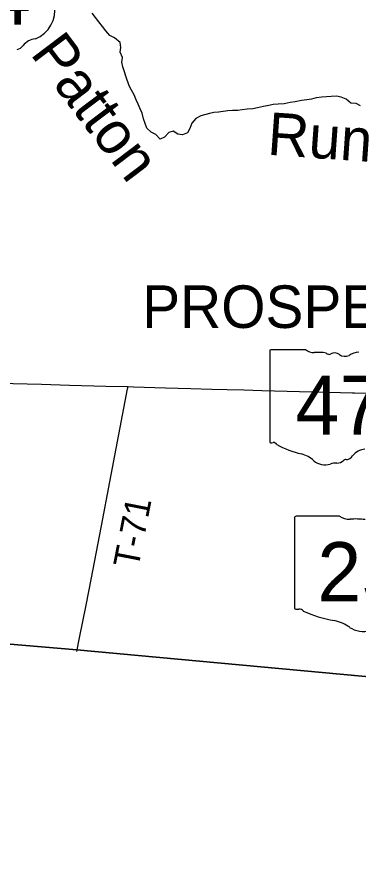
# Model space of a CAD drawing. Extents: x 1584893 to 1934202, y 663575 to 1091909.
# Drawn here: x 1770966 to 1774979, y 887388 to 897514 of the extents above; entities that cross this region are included whole.
import ezdxf

# ---------------------------------------------------------------- set-up
doc = ezdxf.new("R2010")
doc.units = 0
for name, color, linetype in [('GM_X_Adjacent_County', 7, 'Continuous'), ('GM_X_Corporation_Text', 7, 'Continuous'), ('GM_X_County', 7, 'Continuous'), ('GM_X_Minor_River', 7, 'Continuous'), ('GM_X_Minor_River_Text', 7, 'Continuous'), ('GM_X_State_Location', 7, 'Continuous'), ('GM_X_State_Route', 7, 'Continuous'), ('GM_X_State_Shield', 7, 'Continuous'), ('GM_X_Township', 7, 'Continuous'), ('GM_X_Township_Road', 7, 'Continuous'), ('GM_X_Township_Road_Text', 7, 'Continuous')]:
    doc.layers.add(name, color=color, linetype=linetype)

msp = doc.modelspace()

# ---------------------------------------------------------------- linework, layer by layer
at = {"layer": 'GM_X_Adjacent_County'}
msp.add_lwpolyline([(1760161, 891042), (1765804, 890577), (1771666, 890080), (1775269, 889747), (1775894, 889674), (1776032, 889658), (1778209, 889456), (1784657, 889014), (1789933, 888711), (1791146, 888682), (1797651, 888237), (1803655, 887971), (1808445, 887685), (1809126, 887642), (1809339, 887629), (1813443, 887429), (1813717, 887422), (1814360, 887388)], dxfattribs=at)
at = {"layer": 'GM_X_County'}
msp.add_lwpolyline([(1814360, 887388), (1813717, 887422), (1813443, 887429), (1809339, 887629), (1809126, 887642), (1808445, 887685), (1803655, 887971), (1797651, 888237), (1791146, 888682), (1789933, 888711), (1784657, 889014), (1778209, 889456), (1776032, 889658), (1775894, 889674), (1775269, 889747), (1771666, 890080), (1765804, 890577), (1760161, 891042)], dxfattribs=at)
at = {"layer": 'GM_X_Minor_River'}
for points in [[(1773669, 896432), (1773609, 896427), (1773557, 896419), (1773495, 896416), (1773439, 896413), (1773385, 896406), (1773331, 896397), (1773277, 896394), (1773227, 896384), (1773123, 896354), (1773063, 896325), (1773016, 896269), (1772995, 896207), (1772966, 896154), (1772908, 896131), (1772852, 896139), (1772799, 896174), (1772747, 896159), (1772696, 896106), (1772646, 896082), (1772595, 896135), (1772539, 896162), (1772488, 896209), (1772471, 896263), (1772450, 896320), (1772435, 896386), (1772409, 896437), (1772386, 896491), (1772365, 896542), (1772338, 896602), (1772307, 896655), (1772281, 896707), (1772243, 896820), (1772228, 896870), (1772207, 896929), (1772196, 896985), (1772204, 897041), (1772175, 897104), (1772182, 897158), (1772175, 897216), (1772110, 897273), (1772052, 897298), (1772005, 897353), (1771968, 897403), (1771925, 897458), (1771886, 897511), (1771847, 897561)], [(1774999, 896472), (1774948, 896501), (1774888, 896504), (1774833, 896549), (1774771, 896576), (1774716, 896584), (1774654, 896583), (1774600, 896578), (1774544, 896575), (1774478, 896568), (1774422, 896551), (1774368, 896544), (1774306, 896534), (1774231, 896520), (1774173, 896512), (1774101, 896497), (1774033, 896492), (1773973, 896487), (1773923, 896476), (1773859, 896463), (1773791, 896448), (1773735, 896439), (1773669, 896432)]]:
    msp.add_lwpolyline(points, dxfattribs=at)
at = {"layer": 'GM_X_State_Route'}
for points in [[(1770744, 893212), (1771252, 893200), (1771580, 893191), (1772006, 893179), (1772268, 893172), (1772334, 893170), (1772710, 893159), (1773005, 893150), (1773251, 893144), (1773431, 893140), (1773628, 893134), (1773841, 893127), (1774136, 893119), (1774283, 893116), (1774480, 893111), (1774906, 893099), (1774928, 893098)], [(1774928, 893098), (1775070, 893095), (1775201, 893089), (1775299, 893086), (1775403, 893085)]]:
    msp.add_lwpolyline(points, dxfattribs=at)
at = {"layer": 'GM_X_State_Shield'}
for p, q in [((1773933, 893588), (1773933, 892531)), ((1774354, 893606), (1773946, 893606)), ((1774751, 891648), (1774242, 891648)), ((1774225, 891630), (1774225, 890573))]:
    msp.add_line(p, q, dxfattribs=at)
for centre, radius, start, end in [((1771040, 897600), 369, 292.3089, 8.9858), ((1771195, 897057), 202, 94.4031, 142.5768), ((1770939, 897251), 119, 282.8732, 323.2771), ((1773949, 893590), 16.1, 98.1301, 188.1301), ((1774451, 893729), 156, 231.6195, 271.1119), ((1774503, 893013), 562, 80.4867, 94.9883), ((1774631, 893596), 45.1, 219.7921, 297.1024), ((1774697, 893474), 93.8, 54.4667, 119.1411), ((1775017, 893283), 297, 97.3462, 120.7689), ((1774818, 893641), 113, 233.8562, 294.8282), ((1773949, 892529), 16.3, 171.9584, 258.3066), ((1773951, 892637), 124, 267.339, 280.6039), ((1773977, 892470), 44.8, 29.7484, 93.2717), ((1774542, 893420), 1066, 240.4129, 257.1985), ((1774224, 892057), 334, 47.1842, 75.836), ((1774811, 892429), 119, 282.8732, 323.2771), ((1775067, 892235), 202, 94.4031, 142.5768), ((1774585, 892465), 212, 230.7004, 286.2918), ((1774707, 892100), 174, 85.6951, 111.2099), ((1774723, 892386), 113, 268.777, 315.5493), ((1774825, 892284), 31.8, 65.7517, 132.6484)]:
    msp.add_arc(centre, radius, start, end, dxfattribs=at)
for centre, major_axis, start_param, end_param in [((1774245, 891632), (20.2, 0), 1.712693, 3.28349), ((1774873, 891771), (196, 0), 4.042523, 4.731795), ((1774938, 891055), (702, 0), 1.404758, 1.657858), ((1774245, 890571), (20.3, 0), 3.00124, 4.508301), ((1774248, 890679), (155, 0), 4.665946, 4.897461), ((1774280, 890512), (56, 0), 0.519207, 1.627899), ((1774986, 891462), (1333, 0), 4.195997, 4.488961), ((1774589, 890099), (417, 0), 0.823519, 1.323587), ((1775040, 890507), (265, 0), 4.026481, 4.996735)]:
    msp.add_ellipse(centre, major_axis=major_axis, ratio=0.8, start_param=start_param, end_param=end_param, dxfattribs=at)
at = {"layer": 'GM_X_Township'}
msp.add_lwpolyline([(1797651, 888237), (1791146, 888682), (1789933, 888711), (1784657, 889014), (1778209, 889456), (1776032, 889658), (1775894, 889674), (1775269, 889747), (1771666, 890080), (1765804, 890577), (1760161, 891042)], dxfattribs=at)
at = {"layer": 'GM_X_Township_Road'}
msp.add_lwpolyline([(1771666, 890061), (1771698, 890219), (1771775, 890605), (1771837, 890927), (1771911, 891313), (1771955, 891538), (1772053, 892053), (1772235, 893003), (1772263, 893147), (1772268, 893172)], dxfattribs=at)

# ---------------------------------------------------------------- texts
at = {"layer": 'GM_X_Corporation_Text'}
msp.add_text('PROSPECT', height=500, rotation=0, dxfattribs=at).set_placement((1772434, 893862))
at = {"layer": 'GM_X_Minor_River_Text'}
for s, rotation, p in [('Patton', 307.0823, (1771110, 897084)), ('Run', 355.9707, (1773897, 895899))]:
    msp.add_text(s, height=500.1, rotation=rotation, dxfattribs=at).set_placement(p)
at = {"layer": 'GM_X_State_Location'}
for s in ['s', 'r']:
    msp.add_text(s, height=1, dxfattribs=at).set_placement((1774613, 892989))
for s, p in [('47', (1774361, 892917)), ('257', (1774722, 890959))]:
    msp.add_text(s, height=1, rotation=0, dxfattribs=at).set_placement(p)
at = {"layer": 'GM_X_State_Shield'}
for s, height, p in [('4', 696, (1770609, 897428)), ('47', 696.1, (1774235, 892606)), ('257', 696.1, (1774492, 890648))]:
    msp.add_text(s, height=height, dxfattribs=at).set_placement(p)
at = {"layer": 'GM_X_Township_Road_Text'}
msp.add_text('T-71', height=300, rotation=78.9678, dxfattribs=at).set_placement((1772387, 891026))

doc.saveas('drawing.dxf')
